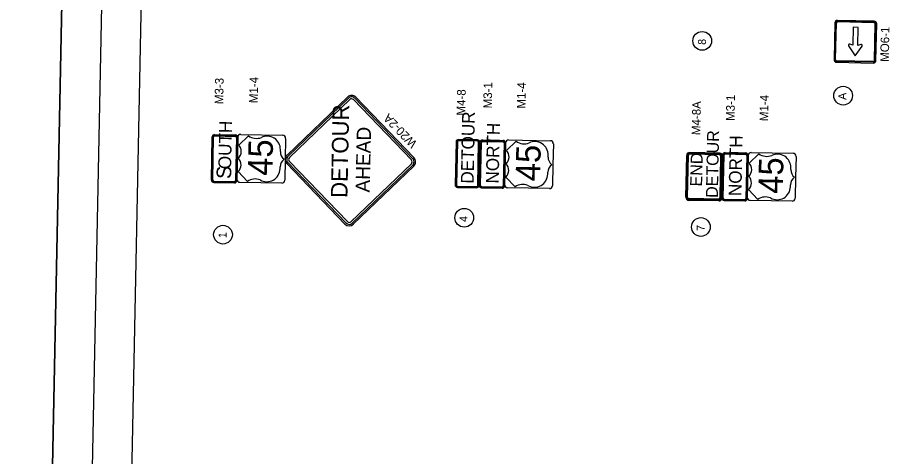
# Model space of a CAD drawing. Extents: x 311409 to 379449, y 121539 to 224848.
# Drawn here: x 311409 to 344745, y 187902 to 204381 of the extents above; entities that cross this region are included whole.
import ezdxf

# ---------------------------------------------------------------- set-up
doc = ezdxf.new("R2010")
doc.units = 0
for name, color, linetype in [('CA-TEXT', 7, 'Continuous'), ('P_RDWY_Text', 7, 'Continuous'), ('P_SGN_Cell', 7, 'Continuous'), ('PLT_Sheet_Border', 7, 'Continuous'), ('PLT_Sheet_Info', 7, 'Continuous')]:
    doc.layers.add(name, color=color, linetype=linetype)

msp = doc.modelspace()

# ---------------------------------------------------------------- linework, layer by layer
at = {"layer": 'CA-TEXT'}
for centre in [(337147, 203512), (342446, 201454), (328200, 196865), (337097, 196517), (319127, 196230)]:
    msp.add_circle(centre, 352, dxfattribs=at)
at = {"layer": 'P_RDWY_Text'}
msp.add_lwpolyline([(311409, 122868), (313463, 224848), (379449, 223519), (377396, 121539)], close=True, dxfattribs=at)
at = {"layer": 'P_SGN_Cell'}
for p, q in [((342133, 204185), (342105, 202807)), ((342131, 202807), (342159, 204185)), ((342164, 202806), (342192, 204184)), ((343610, 204195), (342232, 204223)), ((343611, 204254), (342233, 204282)), ((343611, 204228), (342233, 204255)), ((342819, 204021), (342805, 203348)), ((343016, 204017), (342819, 204021)), ((343002, 203344), (343016, 204017)), ((343621, 202777), (343649, 204155)), ((343654, 202776), (343681, 204154)), ((343680, 202776), (343708, 204154)), ((342805, 203348), (342693, 203385)), ((343116, 203376), (343002, 203344)), ((342648, 203326), (342896, 202949)), ((342896, 202949), (343159, 203315)), ((343580, 202706), (342202, 202733)), ((342202, 202707), (343579, 202679)), ((343581, 202738), (342203, 202766)), ((318689, 198283), (318722, 199904)), ((318712, 198284), (318744, 199904)), ((318742, 198283), (318774, 199903)), ((318813, 199970), (319593, 199954)), ((318813, 199940), (319592, 199924)), ((318814, 199992), (319594, 199977)), ((319629, 199886), (319597, 198266)), ((319659, 199885), (319627, 198266)), ((319682, 199885), (319649, 198265)), ((319650, 198310), (319682, 199885)), ((320082, 199946), (319718, 199597)), ((319796, 199995), (321371, 199963)), ((321481, 199849), (321465, 199061)), ((321481, 199849), (321481, 199849)), ((328756, 198079), (328789, 199699)), ((328779, 198079), (328812, 199699)), ((328809, 198079), (328842, 199698)), ((328880, 199765), (329660, 199749)), ((328880, 199735), (329660, 199719)), ((328881, 199788), (329661, 199772)), ((329696, 199681), (329664, 198062)), ((329726, 199681), (329694, 198061)), ((329749, 199680), (329716, 198060)), ((329717, 198106), (329749, 199681)), ((330149, 199742), (329785, 199393)), ((329864, 199791), (331438, 199759)), ((321285, 199351), (321286, 199422)), ((331549, 199644), (331533, 198857)), ((331549, 199644), (331549, 199644)), ((321465, 199061), (321450, 198274)), ((331352, 199147), (331353, 199218)), ((336532, 197634), (336564, 199208)), ((336561, 197633), (336592, 199208)), ((336598, 197632), (336630, 199207)), ((337803, 199268), (336678, 199291)), ((337802, 199230), (336678, 199253)), ((337804, 199296), (336679, 199319)), ((337817, 197608), (337848, 199183)), ((337854, 197607), (337886, 199182)), ((337882, 197607), (337915, 199227)), ((337882, 197607), (337914, 199181)), ((337905, 197607), (337937, 199227)), ((337935, 197607), (337967, 199226)), ((338006, 199293), (338786, 199277)), ((338006, 199263), (338785, 199247)), ((338007, 199316), (338786, 199300)), ((338822, 199209), (338789, 197589)), ((338852, 199209), (338819, 197589)), ((338875, 199208), (338842, 197588)), ((338843, 197634), (338875, 199209)), ((339275, 199270), (338911, 198920)), ((338989, 199319), (340564, 199287)), ((340674, 199172), (340658, 198385)), ((340674, 199172), (340674, 199172)), ((321272, 198708), (321273, 198779)), ((331533, 198857), (331517, 198070)), ((340478, 198675), (340479, 198746)), ((319698, 198597), (320048, 198232)), ((329765, 198393), (330115, 198028)), ((331339, 198504), (331340, 198575)), ((340658, 198385), (340643, 197598)), ((318777, 198193), (319557, 198177)), ((318778, 198215), (319558, 198199)), ((318779, 198245), (319558, 198229)), ((321335, 198164), (319760, 198195)), ((328846, 198040), (329626, 198025)), ((340465, 198032), (340466, 198103)), ((328845, 198010), (329625, 197995)), ((328845, 197988), (329624, 197972)), ((331402, 197960), (329827, 197991)), ((338891, 197921), (339240, 197556)), ((337768, 197524), (336643, 197547)), ((337767, 197496), (336643, 197519)), ((337769, 197562), (336644, 197585)), ((337970, 197516), (338750, 197500)), ((337971, 197568), (338751, 197553)), ((337971, 197538), (338751, 197523)), ((340528, 197488), (338953, 197519))]:
    msp.add_line(p, q, dxfattribs=at)
for points in [[(323806, 201401), (321535, 199219)], [(323846, 201360), (321574, 199178)], [(326264, 199085), (324082, 201356)], [(326305, 199125), (324123, 201396)], [(323895, 201308), (321624, 199126)], [(326212, 199036), (324031, 201307)], [(327889, 199717), (327857, 198097)], [(327912, 199717), (327879, 198097)], [(327942, 199716), (327909, 198096)], [(328700, 199738), (327980, 199753)], [(328701, 199791), (327981, 199805)], [(328700, 199768), (327981, 199783)], [(328704, 198080), (328737, 199700)], [(328734, 198080), (328767, 199699)], [(328756, 198079), (328789, 199699)], [(321528, 198901), (323710, 196629)], [(321569, 198940), (323751, 196669)], [(321621, 198990), (323803, 196718)], [(323939, 196715), (326211, 198897)], [(323989, 196664), (326261, 198846)], [(324028, 196623), (326300, 198805)], [(327945, 198028), (328665, 198014)], [(327946, 198058), (328666, 198044)], [(327945, 198006), (328665, 197991)]]:
    msp.add_lwpolyline(points, dxfattribs=at)
for centre, radius, start, end in [((342231, 204183), 98.4, 88.8462, 178.8462), ((342231, 204183), 72.2, 88.8462, 178.8462), ((342231, 204183), 39.4, 88.8462, 178.8462), ((343609, 204156), 39.4, 358.8462, 88.8462), ((343609, 204156), 98.4, 358.8462, 88.8462), ((343609, 204156), 72.2, 358.8462, 88.8462), ((342681, 203347), 39.4, 72.0436, 213.3759), ((343127, 203338), 39.4, 324.3166, 105.6488), ((342204, 202805), 98.4, 178.8462, 268.8462), ((342204, 202805), 72.2, 178.8462, 268.8462), ((342204, 202805), 98.4, 239.4497, 268.8462), ((342204, 202805), 39.4, 178.8462, 268.8462), ((343581, 202778), 98.4, 268.8462, 358.8462), ((343581, 202778), 72.2, 268.8462, 358.8462), ((343581, 202778), 39.4, 268.8462, 358.8462), ((323962, 201239), 225, 43.8468, 133.8468), ((323962, 201239), 168, 43.8468, 133.8468), ((323962, 201239), 96.4, 43.8468, 133.8468), ((318812, 199902), 90, 88.8462, 178.8462), ((318812, 199902), 67.5, 88.8462, 178.8462), ((318812, 199902), 37.5, 88.8462, 178.8462), ((319592, 199887), 37.5, 358.8462, 88.8462), ((319592, 199887), 67.5, 358.8462, 88.8462), ((319592, 199887), 90, 358.8462, 88.8462), ((319794, 199883), 112, 88.8462, 178.8462), ((320382, 200346), 500, 233.1143, 291.9873), ((320786, 199432), 500, 358.8462, 115.6928), ((321369, 199851), 112, 358.8462, 88.8462), ((327979, 199715), 90, 88.8468, 178.8468), ((327979, 199715), 67.5, 88.8468, 178.8468), ((327979, 199715), 37.5, 88.8468, 178.8468), ((328699, 199701), 67.5, 358.8468, 88.8468), ((328699, 199701), 37.5, 358.8468, 88.8468), ((328699, 199701), 90, 358.8468, 88.8468), ((328879, 199698), 90, 88.8462, 178.8462), ((328879, 199698), 67.5, 88.8462, 178.8462), ((328879, 199698), 37.5, 88.8462, 178.8462), ((329659, 199682), 67.5, 358.8462, 88.8462), ((329659, 199682), 37.5, 358.8462, 88.8462), ((329659, 199682), 90, 358.8462, 88.8462), ((329861, 199678), 112, 88.8462, 178.8462), ((330449, 200142), 500, 233.1143, 291.9873), ((330853, 199228), 500, 358.8462, 115.6928), ((331436, 199647), 112, 358.8462, 88.8462), ((319458, 199352), 357, 314.4191, 43.2734), ((321646, 199346), 362, 179.1885, 231.634), ((329525, 199148), 357, 314.4191, 43.2734), ((319448, 198852), 357, 314.4191, 43.2734), ((321635, 198770), 362, 126.0584, 178.5039), ((321690, 199057), 225, 133.8449, 223.8468), ((321690, 199057), 168, 133.8449, 223.8468), ((321690, 199057), 96.4, 133.8449, 223.8468), ((326144, 198967), 96.4, 313.854, 44.4977), ((326144, 198967), 168, 313.854, 44.4977), ((326144, 198967), 225, 313.854, 44.4977), ((331713, 199141), 362, 179.1885, 231.634), ((336677, 199206), 112, 88.8468, 178.8468), ((336677, 199206), 84.4, 88.8468, 178.8468), ((336677, 199206), 46.9, 88.8468, 178.8468), ((337801, 199183), 46.9, 358.8468, 88.8468), ((337801, 199183), 84.4, 358.8468, 88.8468), ((337801, 199183), 112, 358.8468, 88.8468), ((338005, 199226), 90, 88.8462, 178.8462), ((338005, 199226), 67.5, 88.8462, 178.8462), ((338005, 199226), 37.5, 88.8462, 178.8462), ((338785, 199210), 37.5, 358.8462, 88.8462), ((338785, 199210), 90, 358.8462, 88.8462), ((338785, 199210), 67.5, 358.8462, 88.8462), ((338987, 199206), 112, 88.8462, 178.8462), ((339575, 199670), 500, 233.1143, 291.9873), ((339979, 198756), 500, 358.8462, 115.6928), ((340562, 199175), 112, 358.8462, 88.8462), ((320772, 198718), 500, 240.0981, 358.8463), ((329515, 198648), 357, 314.4191, 43.2734), ((331702, 198566), 362, 126.0584, 178.5039), ((338651, 198676), 357, 314.4191, 43.2734), ((330839, 198514), 500, 240.0981, 358.8463), ((338641, 198176), 357, 314.4191, 43.2734), ((340828, 198094), 362, 126.0584, 178.5039), ((340839, 198669), 362, 179.1885, 231.634), ((318779, 198283), 90, 179.6119, 268.8462), ((318779, 198283), 67.5, 178.8462, 268.8462), ((318779, 198283), 37.5, 178.8462, 268.8462), ((319559, 198267), 90, 268.8462, 358.8462), ((319559, 198267), 67.5, 268.8462, 358.8462), ((319559, 198267), 37.5, 268.8462, 358.8462), ((319762, 198308), 112, 178.8462, 268.8462), ((320333, 197822), 500, 67.7159, 124.7982), ((321337, 198276), 112, 268.8462, 358.8462), ((327947, 198096), 90, 178.8468, 268.8468), ((327947, 198096), 67.5, 178.8468, 268.8468), ((327947, 198096), 37.5, 178.8468, 268.8468), ((327947, 198096), 37.5, 178.8468, 186.1883), ((328666, 198081), 67.5, 268.8468, 358.8468), ((328666, 198081), 90, 268.8468, 358.8468), ((328666, 198081), 37.5, 268.8468, 358.8468), ((328846, 198078), 90, 179.6119, 268.8462), ((328846, 198078), 67.5, 178.8462, 268.8462), ((328846, 198078), 37.5, 178.8462, 268.8462), ((329626, 198062), 90, 268.8462, 358.8462), ((329626, 198062), 67.5, 268.8462, 358.8462), ((329626, 198062), 37.5, 268.8462, 358.8462), ((329830, 198104), 112, 178.8462, 268.8462), ((330400, 197618), 500, 67.7159, 124.7982), ((331404, 198072), 112, 268.8462, 358.8462), ((339965, 198042), 500, 240.0981, 358.8463), ((336645, 197631), 112, 178.8468, 268.8468), ((336645, 197631), 84.4, 178.8468, 268.8468), ((336645, 197631), 46.9, 178.8468, 268.8468), ((336645, 197631), 46.9, 178.8468, 187.6911), ((337770, 197609), 112, 268.8468, 358.8468), ((337770, 197609), 84.4, 268.8468, 358.8468), ((337770, 197609), 46.9, 268.8468, 358.8468), ((337972, 197606), 90, 179.6119, 268.8462), ((337972, 197606), 67.5, 178.8462, 268.8462), ((337972, 197606), 37.5, 178.8462, 268.8462), ((338752, 197590), 90, 268.8462, 358.8462), ((338752, 197590), 67.5, 268.8462, 358.8462), ((338752, 197590), 37.5, 268.8462, 358.8462), ((338955, 197632), 112, 178.8462, 268.8462), ((339526, 197146), 500, 67.7159, 124.7982), ((340530, 197600), 112, 268.8462, 358.8462), ((323873, 196785), 96.4, 223.8468, 313.8468), ((323873, 196785), 225, 223.8468, 313.8468), ((323873, 196785), 168, 223.8468, 313.8468)]:
    msp.add_arc(centre, radius, start, end, dxfattribs=at)
at = {"layer": 'PLT_Sheet_Border'}
for points in [[(377396, 121539), (379449, 223519), (313463, 224848), (311409, 122868)], [(375910, 122290), (377910, 221569), (314923, 222838), (312923, 123558)]]:
    msp.add_lwpolyline(points, close=True, dxfattribs=at)
at = {"layer": 'PLT_Sheet_Info'}
msp.add_line((314485, 126602), (316388, 221083), dxfattribs=at)

# ---------------------------------------------------------------- texts
at = {"layer": 'CA-TEXT'}
for s, p in [('8', (337287, 203360)), ('A', (342563, 201294)), ('4', (328317, 196705)), ('7', (337237, 196366)), ('1', (319262, 196095))]:
    msp.add_text(s, height=300, rotation=88.8468, dxfattribs=at).set_placement(p)
at = {"layer": 'P_SGN_Cell'}
for s, height, rotation, p in [('MO6-1', 324, 88.8462, (344163, 202721)), ('M3-3', 324, 88.8462, (319134, 201131)), ('M1-4', 324, 88.8462, (320432, 201168)), ('M3-1', 324, 88.8462, (329234, 200972)), ('M1-4', 324, 88.8462, (330500, 200964)), ('M4-8', 324, 88.8468, (328235, 200703)), ('M3-1', 324, 88.8462, (338360, 200500)), ('M1-4', 324, 88.8462, (339625, 200492)), ('DETOUR', 621.4, 88.8468, (323805, 197606)), ('M4-8A', 324, 88.8468, (337074, 199967)), ('W20-2A', 324, 133.8468, (326447, 199676)), ('DETOUR', 480, 88.8468, (328549, 198144)), ('OUTH', 480, 88.8462, (319432, 198687)), ('NORTH', 480, 88.8462, (329493, 198147)), ('AHEAD', 535.7, 88.8468, (324646, 197810)), ('DETOUR', 450, 88.8468, (337734, 197608)), ('45', 920, 88.8462, (320982, 198434)), ('NORTH', 480, 88.8462, (338619, 197675)), ('45', 920, 88.8462, (331049, 198230)), ('END', 450, 88.8468, (337141, 198037)), ('45', 920, 88.8462, (340174, 197758)), ('S', 549, 88.8462, (319432, 198319))]:
    msp.add_text(s, height=height, rotation=rotation, dxfattribs=at).set_placement(p)

doc.saveas('drawing.dxf')
